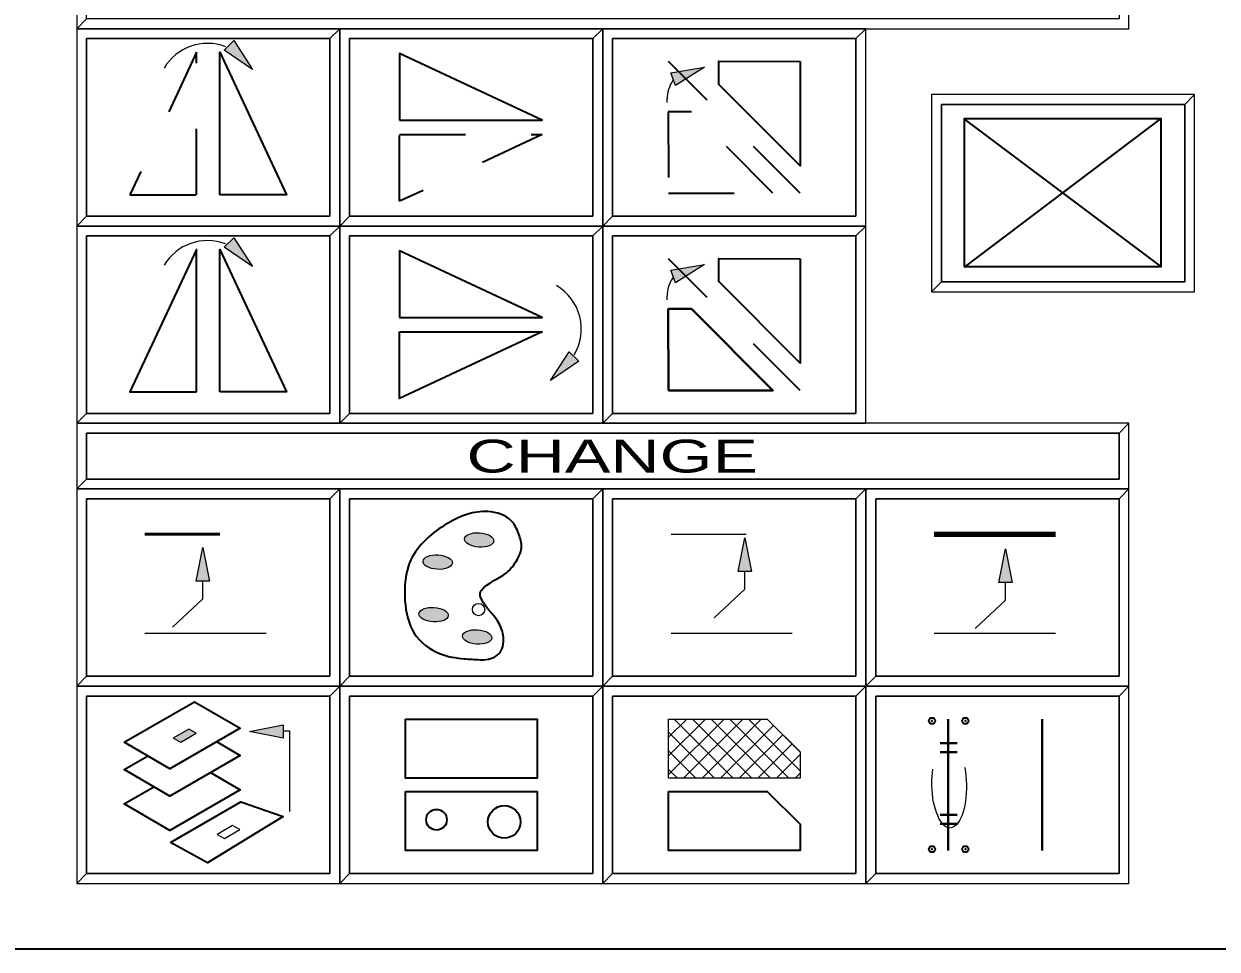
# Model space of a CAD drawing. Extents: x 95906.8 to 95923.6, y 90964.8 to 90972.8.
# Drawn here: x 95912.552 to 95914.366, y 90964.762 to 90966.169 of the extents above; entities that cross this region are included whole.
import ezdxf
from ezdxf.enums import TextEntityAlignment as Align

# ---------------------------------------------------------------- set-up
doc = ezdxf.new("R2010")
doc.units = 0
doc.header["$LTSCALE"] = 0.019
doc.header["$PDMODE"] = 32
doc.header["$PDSIZE"] = 0.0095
doc.linetypes.add('LONG_DASHED', pattern=[7.5, 6, -1.5])
doc.linetypes.add('MEDIUM_DASHED', pattern=[4.5, 3, -1.5])
for name, color, linetype, lineweight in [('1', 7, 'Continuous', 25), ('11', 7, 'Continuous', 25), ('12', 7, 'Continuous', 25), ('16', 7, 'Continuous', 25), ('18', 7, 'Continuous', 25), ('2', 7, 'Continuous', 13), ('3', 7, 'Continuous', 25), ('6', 7, 'Continuous', 35), ('7', 7, 'Continuous', 35)]:
    doc.layers.add(name, color=color, linetype=linetype, lineweight=lineweight)

msp = doc.modelspace()

# ---------------------------------------------------------------- hatches: boundary and pattern name
at = {"layer": '6'}
for points in [[(95912.8712, 90966.1437), (95912.8997, 90966.0999), (95912.8566, 90966.1294)], [(95913.5355, 90966.0945), (95913.587, 90966.1032), (95913.5428, 90966.0755)], [(95912.8712, 90965.8437), (95912.8997, 90965.7999), (95912.8566, 90965.8294)], [(95913.5355, 90965.7945), (95913.587, 90965.8032), (95913.5428, 90965.7755)], [(95913.3959, 90965.656), (95913.3528, 90965.6265), (95913.3813, 90965.6702)], [(95913.6379, 90965.3361), (95913.6481, 90965.3873), (95913.6583, 90965.3361)], [(95912.814, 90965.3216), (95912.8242, 90965.3728), (95912.8344, 90965.3216)], [(95914.0345, 90965.3194), (95914.0447, 90965.3706), (95914.0549, 90965.3194)], [(95912.946, 90965.0826), (95912.8948, 90965.0928), (95912.946, 90965.103)], [(95912.7904, 90965.0764), (95912.8139, 90965.09), (95912.8027, 90965.0964), (95912.7792, 90965.0828)]]:
    msp.add_hatch(color=256, dxfattribs=at).paths.add_polyline_path(points)
h = msp.add_hatch(color=256, dxfattribs=at)
edge = h.paths.add_edge_path()
edge.add_ellipse((95913.2443, 90965.3842), major_axis=(-0.0223, 0.0015), ratio=0.490241, start_angle=0, end_angle=360)
h = msp.add_hatch(color=256, dxfattribs=at)
edge = h.paths.add_edge_path()
edge.add_ellipse((95913.1812, 90965.3504), major_axis=(-0.0223, 0.0015), ratio=0.490241, start_angle=0, end_angle=360)
h = msp.add_hatch(color=256, dxfattribs=at)
edge = h.paths.add_edge_path()
edge.add_ellipse((95913.1751, 90965.2705), major_axis=(-0.0223, 0.0015), ratio=0.490241, start_angle=0, end_angle=360)
h = msp.add_hatch(color=256, dxfattribs=at)
edge = h.paths.add_edge_path()
edge.add_ellipse((95913.2412, 90965.2366), major_axis=(-0.0223, 0.0015), ratio=0.490241, start_angle=0, end_angle=360)

# ---------------------------------------------------------------- linework, layer by layer
at = {"layer": '1'}
for points in [[(95912.6323, 90966.1617), (95914.2323, 90966.1617), (95914.2323, 90966.2617), (95912.6323, 90966.2617)], [(95912.6323, 90965.8617), (95913.0323, 90965.8617), (95913.0323, 90966.1617), (95912.6323, 90966.1617)], [(95913.0323, 90965.8617), (95913.4323, 90965.8617), (95913.4323, 90966.1617), (95913.0323, 90966.1617)], [(95913.4323, 90965.8617), (95913.8323, 90965.8617), (95913.8323, 90966.1617), (95913.4323, 90966.1617)], [(95913.9323, 90965.7617), (95914.3323, 90965.7617), (95914.3323, 90966.0617), (95913.9323, 90966.0617)], [(95912.6323, 90965.5617), (95913.0323, 90965.5617), (95913.0323, 90965.8617), (95912.6323, 90965.8617)], [(95913.0323, 90965.5617), (95913.4323, 90965.5617), (95913.4323, 90965.8617), (95913.0323, 90965.8617)], [(95913.4323, 90965.5617), (95913.8323, 90965.5617), (95913.8323, 90965.8617), (95913.4323, 90965.8617)], [(95912.6323, 90965.4617), (95914.2323, 90965.4617), (95914.2323, 90965.5617), (95912.6323, 90965.5617)], [(95912.6323, 90965.1617), (95913.0323, 90965.1617), (95913.0323, 90965.4617), (95912.6323, 90965.4617)], [(95913.0323, 90965.1617), (95913.4323, 90965.1617), (95913.4323, 90965.4617), (95913.0323, 90965.4617)], [(95913.4323, 90965.1617), (95913.8323, 90965.1617), (95913.8323, 90965.4617), (95913.4323, 90965.4617)], [(95913.8323, 90965.1617), (95914.2323, 90965.1617), (95914.2323, 90965.4617), (95913.8323, 90965.4617)], [(95912.6323, 90964.8617), (95913.0323, 90964.8617), (95913.0323, 90965.1617), (95912.6323, 90965.1617)], [(95913.0323, 90964.8617), (95913.4323, 90964.8617), (95913.4323, 90965.1617), (95913.0323, 90965.1617)], [(95913.4323, 90964.8617), (95913.8323, 90964.8617), (95913.8323, 90965.1617), (95913.4323, 90965.1617)], [(95913.8323, 90964.8617), (95914.2323, 90964.8617), (95914.2323, 90965.1617), (95913.8323, 90965.1617)]]:
    msp.add_lwpolyline(points, close=True, dxfattribs=at)
at = {"layer": '11'}
for points in [[(95913.0473, 90965.8767), (95913.4173, 90965.8767), (95913.4173, 90966.1467), (95913.0473, 90966.1467)], [(95913.4473, 90965.8767), (95913.8173, 90965.8767), (95913.8173, 90966.1467), (95913.4473, 90966.1467)], [(95912.6473, 90965.5767), (95913.0173, 90965.5767), (95913.0173, 90965.8467), (95912.6473, 90965.8467)], [(95913.0473, 90965.5767), (95913.4173, 90965.5767), (95913.4173, 90965.8467), (95913.0473, 90965.8467)], [(95913.4473, 90965.5767), (95913.8173, 90965.5767), (95913.8173, 90965.8467), (95913.4473, 90965.8467)], [(95912.6473, 90965.1767), (95913.0173, 90965.1767), (95913.0173, 90965.4467), (95912.6473, 90965.4467)], [(95913.0473, 90965.1767), (95913.4173, 90965.1767), (95913.4173, 90965.4467), (95913.0473, 90965.4467)], [(95913.4473, 90965.1767), (95913.8173, 90965.1767), (95913.8173, 90965.4467), (95913.4473, 90965.4467)], [(95912.6473, 90964.8767), (95913.0173, 90964.8767), (95913.0173, 90965.1467), (95912.6473, 90965.1467)], [(95913.0473, 90964.8767), (95913.4173, 90964.8767), (95913.4173, 90965.1467), (95913.0473, 90965.1467)], [(95913.4473, 90964.8767), (95913.8173, 90964.8767), (95913.8173, 90965.1467), (95913.4473, 90965.1467)], [(95913.8473, 90964.8767), (95914.2173, 90964.8767), (95914.2173, 90965.1467), (95913.8473, 90965.1467)]]:
    msp.add_lwpolyline(points, close=True, dxfattribs=at)
at = {"layer": '12'}
for points in [[(95912.6473, 90965.8767), (95913.0173, 90965.8767), (95913.0173, 90966.1467), (95912.6473, 90966.1467)], [(95913.8473, 90965.1767), (95914.2173, 90965.1767), (95914.2173, 90965.4467), (95913.8473, 90965.4467)]]:
    msp.add_lwpolyline(points, close=True, dxfattribs=at)
at = {"layer": '16'}
msp.add_lwpolyline([(95913.9473, 90965.7767), (95914.3173, 90965.7767), (95914.3173, 90966.0467), (95913.9473, 90966.0467)], close=True, dxfattribs=at)
msp.add_lwpolyline([(95913.9473, 90965.7767), (95914.3173, 90965.7767), (95914.3173, 90966.0467), (95913.9473, 90966.0467)], close=True, dxfattribs=at)
at = {"layer": '18'}
msp.add_lwpolyline([(95912.6473, 90965.4767), (95914.2173, 90965.4767), (95914.2173, 90965.5467), (95912.6473, 90965.5467)], close=True, dxfattribs=at)
at = {"layer": '2'}
for points in [[(95912.6323, 90966.2617), (95912.6323, 90966.1617), (95912.6473, 90966.1767), (95912.6473, 90966.2467), (95914.2173, 90966.2467), (95914.2323, 90966.2617)], [(95912.6323, 90966.1617), (95912.6323, 90965.8617), (95912.6473, 90965.8767), (95912.6473, 90966.1467), (95913.0173, 90966.1467), (95913.0323, 90966.1617)], [(95913.0323, 90966.1617), (95913.0323, 90965.8617), (95913.0473, 90965.8767), (95913.0473, 90966.1467), (95913.4173, 90966.1467), (95913.4323, 90966.1617)], [(95913.4323, 90966.1617), (95913.4323, 90965.8617), (95913.4473, 90965.8767), (95913.4473, 90966.1467), (95913.8173, 90966.1467), (95913.8323, 90966.1617)], [(95913.9323, 90966.0617), (95913.9323, 90965.7617), (95913.9473, 90965.7767), (95913.9473, 90966.0467), (95914.3173, 90966.0467), (95914.3323, 90966.0617)], [(95912.6323, 90965.8617), (95912.6323, 90965.5617), (95912.6473, 90965.5767), (95912.6473, 90965.8467), (95913.0173, 90965.8467), (95913.0323, 90965.8617)], [(95913.0323, 90965.8617), (95913.0323, 90965.5617), (95913.0473, 90965.5767), (95913.0473, 90965.8467), (95913.4173, 90965.8467), (95913.4323, 90965.8617)], [(95913.4323, 90965.8617), (95913.4323, 90965.5617), (95913.4473, 90965.5767), (95913.4473, 90965.8467), (95913.8173, 90965.8467), (95913.8323, 90965.8617)], [(95912.6323, 90965.5617), (95912.6323, 90965.4617), (95912.6473, 90965.4767), (95912.6473, 90965.5467), (95914.2173, 90965.5467), (95914.2323, 90965.5617)], [(95912.6323, 90965.4617), (95912.6323, 90965.1617), (95912.6473, 90965.1767), (95912.6473, 90965.4467), (95913.0173, 90965.4467), (95913.0323, 90965.4617)], [(95913.0323, 90965.4617), (95913.0323, 90965.1617), (95913.0473, 90965.1767), (95913.0473, 90965.4467), (95913.4173, 90965.4467), (95913.4323, 90965.4617)], [(95913.4323, 90965.4617), (95913.4323, 90965.1617), (95913.4473, 90965.1767), (95913.4473, 90965.4467), (95913.8173, 90965.4467), (95913.8323, 90965.4617)], [(95913.8323, 90965.4617), (95913.8323, 90965.1617), (95913.8473, 90965.1767), (95913.8473, 90965.4467), (95914.2173, 90965.4467), (95914.2323, 90965.4617)], [(95912.6323, 90965.1617), (95912.6323, 90964.8617), (95912.6473, 90964.8767), (95912.6473, 90965.1467), (95913.0173, 90965.1467), (95913.0323, 90965.1617)], [(95913.0323, 90965.1617), (95913.0323, 90964.8617), (95913.0473, 90964.8767), (95913.0473, 90965.1467), (95913.4173, 90965.1467), (95913.4323, 90965.1617)], [(95913.4323, 90965.1617), (95913.4323, 90964.8617), (95913.4473, 90964.8767), (95913.4473, 90965.1467), (95913.8173, 90965.1467), (95913.8323, 90965.1617)], [(95913.8323, 90965.1617), (95913.8323, 90964.8617), (95913.8473, 90964.8767), (95913.8473, 90965.1467), (95914.2173, 90965.1467), (95914.2323, 90965.1617)]]:
    msp.add_lwpolyline(points, close=True, dxfattribs=at)
at = {"layer": '3'}
for points in [[(95912.6323, 90966.1617), (95914.2323, 90966.1617), (95914.2323, 90966.2617), (95914.2173, 90966.2467), (95914.2173, 90966.1767), (95912.6473, 90966.1767)], [(95912.6323, 90965.8617), (95913.0323, 90965.8617), (95913.0323, 90966.1617), (95913.0173, 90966.1467), (95913.0173, 90965.8767), (95912.6473, 90965.8767)], [(95913.0323, 90965.8617), (95913.4323, 90965.8617), (95913.4323, 90966.1617), (95913.4173, 90966.1467), (95913.4173, 90965.8767), (95913.0473, 90965.8767)], [(95913.4323, 90965.8617), (95913.8323, 90965.8617), (95913.8323, 90966.1617), (95913.8173, 90966.1467), (95913.8173, 90965.8767), (95913.4473, 90965.8767)], [(95913.9323, 90965.7617), (95914.3323, 90965.7617), (95914.3323, 90966.0617), (95914.3173, 90966.0467), (95914.3173, 90965.7767), (95913.9473, 90965.7767)], [(95912.6323, 90965.5617), (95913.0323, 90965.5617), (95913.0323, 90965.8617), (95913.0173, 90965.8467), (95913.0173, 90965.5767), (95912.6473, 90965.5767)], [(95913.0323, 90965.5617), (95913.4323, 90965.5617), (95913.4323, 90965.8617), (95913.4173, 90965.8467), (95913.4173, 90965.5767), (95913.0473, 90965.5767)], [(95913.4323, 90965.5617), (95913.8323, 90965.5617), (95913.8323, 90965.8617), (95913.8173, 90965.8467), (95913.8173, 90965.5767), (95913.4473, 90965.5767)], [(95912.6323, 90965.4617), (95914.2323, 90965.4617), (95914.2323, 90965.5617), (95914.2173, 90965.5467), (95914.2173, 90965.4767), (95912.6473, 90965.4767)], [(95912.6323, 90965.1617), (95913.0323, 90965.1617), (95913.0323, 90965.4617), (95913.0173, 90965.4467), (95913.0173, 90965.1767), (95912.6473, 90965.1767)], [(95913.0323, 90965.1617), (95913.4323, 90965.1617), (95913.4323, 90965.4617), (95913.4173, 90965.4467), (95913.4173, 90965.1767), (95913.0473, 90965.1767)], [(95913.4323, 90965.1617), (95913.8323, 90965.1617), (95913.8323, 90965.4617), (95913.8173, 90965.4467), (95913.8173, 90965.1767), (95913.4473, 90965.1767)], [(95913.8323, 90965.1617), (95914.2323, 90965.1617), (95914.2323, 90965.4617), (95914.2173, 90965.4467), (95914.2173, 90965.1767), (95913.8473, 90965.1767)], [(95912.6323, 90964.8617), (95913.0323, 90964.8617), (95913.0323, 90965.1617), (95913.0173, 90965.1467), (95913.0173, 90964.8767), (95912.6473, 90964.8767)], [(95913.0323, 90964.8617), (95913.4323, 90964.8617), (95913.4323, 90965.1617), (95913.4173, 90965.1467), (95913.4173, 90964.8767), (95913.0473, 90964.8767)], [(95913.4323, 90964.8617), (95913.8323, 90964.8617), (95913.8323, 90965.1617), (95913.8173, 90965.1467), (95913.8173, 90964.8767), (95913.4473, 90964.8767)], [(95913.8323, 90964.8617), (95914.2323, 90964.8617), (95914.2323, 90965.1617), (95914.2173, 90965.1467), (95914.2173, 90964.8767), (95913.8473, 90964.8767)]]:
    msp.add_lwpolyline(points, close=True, dxfattribs=at)
at = {"layer": '6', "linetype": 'MEDIUM_DASHED'}
for p, q in [((95913.7323, 90965.9117), (95913.5323, 90966.1117)), ((95913.7323, 90965.6117), (95913.5323, 90965.8117))]:
    msp.add_line(p, q, dxfattribs=at)
at = {"layer": '6', "lineweight": 25}
for p, q in [((95913.5301, 90966.0495), (95913.5301, 90966.0549)), ((95913.5301, 90965.7495), (95913.5301, 90965.7549)), ((95912.7361, 90965.2424), (95912.9205, 90965.2424)), ((95913.9361, 90965.2424), (95914.1205, 90965.2424))]:
    msp.add_line(p, q, dxfattribs=at)
at = {"layer": '6'}
for p, q in [((95913.9815, 90966.0248), (95914.2815, 90965.7998)), ((95913.9823, 90965.7989), (95914.2815, 90966.0251))]:
    msp.add_line(p, q, dxfattribs=at)
at = {"layer": '6', "linetype": 'LONG_DASHED', "lineweight": 53}
msp.add_line((95912.7361, 90965.393), (95912.9205, 90965.393), dxfattribs=at)
at = {"layer": '6', "linetype": 'LONG_DASHED', "lineweight": 13}
msp.add_line((95913.5361, 90965.393), (95913.7205, 90965.393), dxfattribs=at)
at = {"layer": '6', "lineweight": 158}
msp.add_line((95913.9361, 90965.393), (95914.1205, 90965.393), dxfattribs=at)
at = {"layer": '6', "lineweight": 13}
for p, q in [((95913.5361, 90965.2424), (95913.7205, 90965.2424)), ((95913.5323, 90965.0273), (95913.6167, 90965.1117)), ((95913.5323, 90965.0556), (95913.5884, 90965.1117)), ((95913.5323, 90965.0839), (95913.5601, 90965.1117)), ((95913.5406, 90965.1117), (95913.6306, 90965.0217)), ((95913.555, 90965.0217), (95913.645, 90965.1117)), ((95913.5688, 90965.1117), (95913.6588, 90965.0217)), ((95913.5832, 90965.0217), (95913.6732, 90965.1117)), ((95913.5971, 90965.1117), (95913.6871, 90965.0217)), ((95913.6115, 90965.0217), (95913.6919, 90965.1021)), ((95913.6254, 90965.1117), (95913.7154, 90965.0217)), ((95913.6537, 90965.1117), (95913.7323, 90965.0331)), ((95913.682, 90965.1117), (95913.7323, 90965.0614)), ((95913.5323, 90965.0917), (95913.6023, 90965.0217)), ((95913.6398, 90965.0217), (95913.7061, 90965.0879)), ((95913.5323, 90965.0634), (95913.574, 90965.0217)), ((95913.6681, 90965.0217), (95913.7202, 90965.0738)), ((95913.6964, 90965.0217), (95913.7323, 90965.0576)), ((95913.5323, 90965.0351), (95913.5457, 90965.0217)), ((95913.7247, 90965.0217), (95913.7323, 90965.0293))]:
    msp.add_line(p, q, dxfattribs=at)
at = {"layer": '6', "lineweight": 40}
for p, q in [((95913.9573, 90965.1117), (95913.9573, 90964.9117)), ((95914.1003, 90965.1117), (95914.1003, 90964.9117)), ((95913.9451, 90965.0752), (95913.9713, 90965.0752)), ((95913.9451, 90965.0614), (95913.9713, 90965.0614)), ((95913.9451, 90964.9661), (95913.9713, 90964.9661)), ((95913.9451, 90964.9522), (95913.9713, 90964.9522))]:
    msp.add_line(p, q, dxfattribs=at)
at = {"layer": '6', "lineweight": 25}
for points in [[(95912.8712, 90966.1437), (95912.8997, 90966.0999), (95912.8566, 90966.1294)], [(95913.5355, 90966.0945), (95913.587, 90966.1032), (95913.5428, 90966.0755)], [(95912.8712, 90965.8437), (95912.8997, 90965.7999), (95912.8566, 90965.8294)], [(95913.5355, 90965.7945), (95913.587, 90965.8032), (95913.5428, 90965.7755)], [(95913.3959, 90965.656), (95913.3528, 90965.6265), (95913.3813, 90965.6702)], [(95913.6379, 90965.3361), (95913.6481, 90965.3873), (95913.6583, 90965.3361)], [(95912.814, 90965.3216), (95912.8242, 90965.3728), (95912.8344, 90965.3216)], [(95914.0345, 90965.3194), (95914.0447, 90965.3706), (95914.0549, 90965.3194)], [(95912.946, 90965.0826), (95912.8948, 90965.0928), (95912.946, 90965.103)], [(95913.5323, 90965.1117), (95913.6823, 90965.1117), (95913.7323, 90965.0617), (95913.7323, 90965.0217), (95913.5323, 90965.0217)], [(95912.7904, 90965.0764), (95912.8139, 90965.09), (95912.8027, 90965.0964), (95912.7792, 90965.0828)]]:
    msp.add_lwpolyline(points, close=True, dxfattribs=at)
at = {"layer": '6', "linetype": 'MEDIUM_DASHED'}
for points in [[(95912.8146, 90965.9093), (95912.8146, 90966.126), (95912.7132, 90965.9093)], [(95913.5323, 90965.9117), (95913.6909, 90965.9117), (95913.567, 90966.0356), (95913.5317, 90966.0356)], [(95913.1234, 90966.0007), (95913.3401, 90966.0007), (95913.1234, 90965.8993)]]:
    msp.add_lwpolyline(points, close=True, dxfattribs=at)
at = {"layer": '6'}
for points in [[(95912.85, 90965.9093), (95912.85, 90966.126), (95912.9514, 90965.9093)], [(95913.1234, 90966.0227), (95913.3401, 90966.0227), (95913.1234, 90966.1241)], [(95913.7324, 90966.1118), (95913.7324, 90965.9532), (95913.6085, 90966.0771), (95913.6085, 90966.1124)], [(95913.9816, 90965.7999), (95914.2816, 90965.7999), (95914.2816, 90966.0249), (95913.9816, 90966.0249)], [(95912.8146, 90965.6093), (95912.8146, 90965.826), (95912.7132, 90965.6093)], [(95912.85, 90965.6093), (95912.85, 90965.826), (95912.9514, 90965.6093)], [(95913.1234, 90965.7227), (95913.3401, 90965.7227), (95913.1234, 90965.8241)], [(95913.7324, 90965.8118), (95913.7324, 90965.6532), (95913.6085, 90965.7771), (95913.6085, 90965.8124)], [(95913.1234, 90965.7007), (95913.3401, 90965.7007), (95913.1234, 90965.5993)], [(95912.7043, 90965.0763), (95912.8113, 90965.1381), (95912.8811, 90965.0978), (95912.7741, 90965.036)], [(95913.1323, 90965.1117), (95913.3323, 90965.1117), (95913.3323, 90965.0217), (95913.1323, 90965.0217)], [(95913.1323, 90965.0017), (95913.3323, 90965.0017), (95913.3323, 90964.9117), (95913.1323, 90964.9117)], [(95913.5323, 90965.0017), (95913.6823, 90965.0017), (95913.7323, 90964.9517), (95913.7323, 90964.9117), (95913.5323, 90964.9117)], [(95912.775, 90964.9241), (95912.882, 90964.9859), (95912.9463, 90964.9636), (95912.8314, 90964.8932)]]:
    msp.add_lwpolyline(points, close=True, dxfattribs=at)
at = {"layer": '6', "lineweight": 40}
msp.add_lwpolyline([(95913.5323, 90965.6117), (95913.6909, 90965.6117), (95913.567, 90965.7356), (95913.5317, 90965.7356)], close=True, dxfattribs=at)
at = {"layer": '6', "lineweight": 25}
for points in [[(95913.6018, 90965.2659), (95913.6481, 90965.3093), (95913.6481, 90965.3361)], [(95912.7779, 90965.2514), (95912.8242, 90965.2948), (95912.8242, 90965.3216)], [(95913.9984, 90965.2492), (95914.0447, 90965.2926), (95914.0447, 90965.3194)], [(95912.9565, 90964.9712), (95912.9565, 90965.0934), (95912.949, 90965.0934), (95912.946, 90965.0934)]]:
    msp.add_lwpolyline(points, dxfattribs=at)
at = {"layer": '6'}
for points in [[(95912.8448, 90965.0774), (95912.8811, 90965.0563), (95912.7741, 90964.9945), (95912.7043, 90965.0348), (95912.74, 90965.0554)], [(95912.8357, 90965.0303), (95912.8811, 90965.004), (95912.7741, 90964.9422), (95912.7043, 90964.9825), (95912.7496, 90965.0087)]]:
    msp.add_lwpolyline(points, dxfattribs=at)
at = {"layer": '6', "linetype": 'MEDIUM_DASHED', "lineweight": 13}
msp.add_lwpolyline([(95912.857, 90964.9299), (95912.8805, 90964.9435), (95912.8693, 90964.9499), (95912.8458, 90964.9363)], close=True, dxfattribs=at)
at = {"layer": '6', "lineweight": 25}
msp.add_circle((95913.2435, 90965.2782), 0.00934, dxfattribs=at)
at = {"layer": '6'}
for centre, radius in [((95913.1794, 90964.9585), 0.0157), ((95913.2825, 90964.9553), 0.0248)]:
    msp.add_circle(centre, radius, dxfattribs=at)
at = {"layer": '6', "lineweight": 25}
for centre, radius, start, end in [((95912.8311, 90966.0628), 0.0767, 69.0308, 149.3662), ((95913.5801, 90966.0549), 0.05, 145.9676, 180), ((95912.8311, 90965.7628), 0.0767, 69.0308, 149.3662), ((95913.3229, 90965.705), 0.0767, 329.1884, 59.3661), ((95913.5801, 90965.7549), 0.05, 145.9676, 180)]:
    msp.add_arc(centre, radius, start, end, dxfattribs=at)
for centre in [(95913.2443, 90965.3842), (95913.1812, 90965.3504), (95913.1751, 90965.2705), (95913.2412, 90965.2366)]:
    msp.add_ellipse(centre, major_axis=(-0.0223, 0.0015), ratio=0.490241, dxfattribs=at)
at = {"layer": '6', "linetype": 'MEDIUM_DASHED', "lineweight": 13}
msp.add_ellipse((95913.959, 90965.0115), major_axis=(0.0015, -0.0654), ratio=0.400869, dxfattribs=at)
at = {"layer": '6'}
msp.add_spline([(95913.2456, 90965.202), (95913.2218, 90965.2034), (95913.184, 90965.2114), (95913.1462, 90965.2415), (95913.1315, 90965.2918), (95913.1405, 90965.3537), (95913.1959, 90965.4091), (95913.2577, 90965.4273), (95913.2935, 90965.4129), (95913.3045, 90965.3928), (95913.3085, 90965.3724), (95913.2992, 90965.3497), (95913.2858, 90965.3343), (95913.2459, 90965.3035), (95913.2727, 90965.2603), (95913.2808, 90965.2392), (95913.2761, 90965.2131), (95913.2513, 90965.202), (95913.2456, 90965.202)], degree=3, dxfattribs=at)
for p in [(95913.9328, 90965.109), (95913.9836, 90965.109), (95913.9328, 90964.9138), (95913.9836, 90964.9138)]:
    msp.add_point(p, dxfattribs=at)
at = {"layer": '7'}
msp.add_lwpolyline([(95906.8323, 90972.7617), (95918.8323, 90972.7617), (95918.8323, 90964.7617), (95906.8323, 90964.7617)], close=True, dxfattribs=at)

# ---------------------------------------------------------------- texts
at = {"layer": '7', "width": 1.55}
msp.add_text('         CHANGE        ', height=0.04999, dxfattribs=at).set_placement((95913.4323, 90965.4867), align=Align.CENTER)

doc.saveas('drawing.dxf')
